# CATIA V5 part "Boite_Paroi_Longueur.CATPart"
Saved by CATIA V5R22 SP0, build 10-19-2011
Part number: Boite_Paroi_Longueur
Bounding box of the stored display mesh (mm): x -88 to 88, y 0 to 5, z -17.5 to 17.5
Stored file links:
  U:\S9A\PER\CAO\Assemblage\Reservoir_Boite\Boite\Boite_Paroi_Longueur.CATPart
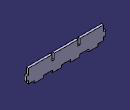
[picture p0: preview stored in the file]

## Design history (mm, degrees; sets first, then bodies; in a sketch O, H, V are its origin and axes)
Body1 (main body)
  Sketch1 on zx-plane, origin (0, 0, 0), H (-1, 0, 0), V (0, 0, 1)
    line L1 (-88, 17.5) -> (88, 17.5)
    line L2 (88, 17.5) -> (88, -17.5)
    line L3 (88, -17.5) -> (-88, -17.5)
    line L4 (-88, -17.5) -> (-88, 17.5)
    length L1 = 176
    length L4 = 35
    horizontal: L1 H, L3 H
    vertical: L2 V, L4 V
    symmetry: L4 L2 V, L3 L1 H
  Pad1: profile Sketch1, direction (0, 1, 0), length 5
  Sketch2 on end face of Pad1, origin (0, 5, 0), H (-1, 0, 0), V (0, 0, 1)
    point P1 (-88, -17.5)
    line L1 (-88, -17.5) -> (-70, -17.5)
    line L2 (-70, -17.5) -> (-70, -12.5)
    line L3 (-70, -12.5) -> (-88, -12.5)
    line L4 (-88, -12.5) -> (-88, -17.5)
    point P2 (-70, -17.5)
    point P3 (-70, -12.5)
    point P4 (-88, -12.5)
    reference projected point E1 (-88, -17.5) from vertex [face of Pad1 from Sketch1.L3 | end face of Pad1 | face of Pad1 from Sketch1.L4]
    point P5 (88, -17.5)
    point P6 (70, -17.5)
    point P7 (70, -12.5)
    point P8 (88, -12.5)
    line L5 (88, -17.5) -> (70, -17.5)
    line L6 (70, -17.5) -> (70, -12.5)
    line L7 (70, -12.5) -> (88, -12.5)
    line L8 (88, -12.5) -> (88, -17.5)
    length L4 = 5
    length L1 = 18
    horizontal: L1 H, L3 H
    vertical: L2 V, L4 V
    coincidence: P1 E1
    symmetry: P1 P5 V, P2 P6 V, P3 P7 V, P4 P8 V, L1 L5 V, L2 L6 V, L3 L7 V, L4 L8 V
  Pocket1: profile Sketch2, direction (0, -1, 0), through (limit type 6)
  Sketch3 on end face of Pad1, origin (0, 5, 0), H (-1, 0, 0), V (0, 0, 1)
    point P1 (-88, 17.5)
    line L1 (-88, 17.5) -> (-83, 17.5)
    line L2 (-83, 17.5) -> (-83, 4.5)
    line L3 (-83, 4.5) -> (-88, 4.5)
    line L4 (-88, 4.5) -> (-88, 17.5)
    point P2 (-83, 17.5)
    point P3 (-83, 4.5)
    point P4 (-88, 4.5)
    reference projected point E1 (-88, 17.5) from vertex [face of Pad1 from Sketch1.L1 | end face of Pad1 | face of Pad1 from Sketch1.L4]
    point P5 (-88, -5.5)
    line L5 (-88, -5.5) -> (-83, -5.5)
    line L6 (-83, -5.5) -> (-83, -12.5)
    line L7 (-83, -12.5) -> (-88, -12.5)
    line L8 (-88, -12.5) -> (-88, -5.5)
    point P6 (-83, -5.5)
    point P7 (-83, -12.5)
    point P8 (-88, -12.5)
    reference projected point E2 (-88, -12.5) from vertex [end face of Pad1 | face of Pad1 from Sketch1.L4 | face of Pocket1 from Sketch2.L3]
    point P9 (88, 17.5)
    point P10 (83, 17.5)
    point P11 (83, 4.5)
    point P12 (88, 4.5)
    point P13 (88, -5.5)
    point P14 (83, -5.5)
    point P15 (83, -12.5)
    point P16 (88, -12.5)
    line L9 (88, 17.5) -> (83, 17.5)
    line L10 (83, 17.5) -> (83, 4.5)
    line L11 (83, 4.5) -> (88, 4.5)
    line L12 (88, 4.5) -> (88, 17.5)
    line L13 (88, -5.5) -> (83, -5.5)
    line L14 (83, -5.5) -> (83, -12.5)
    line L15 (83, -12.5) -> (88, -12.5)
    line L16 (88, -12.5) -> (88, -5.5)
    length L4 = 13
    length L8 = 7
    length L1 = 5
    horizontal: L1 H, L3 H, L5 H, L7 H
    vertical: L2 V, L4 V, L6 V, L8 V
    coincidence: P1 E1, P8 E2, L6 L2
    symmetry: P1 P9 V, P2 P10 V, P3 P11 V, P4 P12 V, P5 P13 V, P6 P14 V, P7 P15 V, P8 P16 V, L1 L9 V, L2 L10 V, L3 L11 V, L4 L12 V, L5 L13 V, L6 L14 V, L7 L15 V, L8 L16 V
  Pocket2: profile Sketch3, direction (0, -1, 0), through (limit type 6)
  Sketch4 on end face of Pad1, origin (0, 5, 0), H (-1, 0, 0), V (0, 0, 1)
    line L1 (-50, -12.5) -> (-30, -12.5)
    line L2 (-30, -12.5) -> (-30, -17.5)
    line L3 (-30, -17.5) -> (-50, -17.5)
    line L4 (-50, -17.5) -> (-50, -12.5)
    reference projected line E1 (-88, -17.5) -> (88, -17.5) from edge [face of Pad1 from Sketch1.L3 | end face of Pad1]
    reference projected line E2 (-70, -17.5) -> (-70, -12.5) from edge [end face of Pad1 | face of Pocket1 from Sketch2.L2]
    reference projected line E3 (-70, -12.5) -> (-88, -12.5) from edge [end face of Pad1 | face of Pocket1 from Sketch2.L3]
    distance L4 E2 = 20
    length L3 = 20
    horizontal: L1 H, L3 H
    vertical: L2 V, L4 V
    coincidence: L3 E1, L1 E3
  Pocket3: profile Sketch4, direction (0, -1, 0), through (limit type 6)
  RectPattern1: of Pocket3, direction 1 instances 3, spacing 40, along edge [face of Pad1 from Sketch1.L3 | end face of Pad1]
  Sketch5 on end face of Pad1, origin (0, 5, 0), H (-1, 0, 0), V (0, 0, 1)
    point P1 (-31, 17.5)
    line L1 (-31, 17.5) -> (-26, 17.5)
    line L2 (-26, 17.5) -> (-26, 5.5)
    line L3 (-26, 5.5) -> (-31, 5.5)
    line L4 (-31, 5.5) -> (-31, 17.5)
    point P2 (-26, 17.5)
    point P3 (-26, 5.5)
    point P4 (-31, 5.5)
    reference projected line E1 (88, 17.5) -> (-88, 17.5) from edge [face of Pad1 from Sketch1.L1 | end face of Pad1]
    point P5 (31, 17.5)
    point P6 (26, 17.5)
    point P7 (26, 5.5)
    point P8 (31, 5.5)
    line L5 (31, 17.5) -> (26, 17.5)
    line L6 (26, 17.5) -> (26, 5.5)
    line L7 (26, 5.5) -> (31, 5.5)
    line L8 (31, 5.5) -> (31, 17.5)
    length L1 = 5
    length L4 = 12
    distance L2 V = 26
    horizontal: L1 H, L3 H
    vertical: L2 V, L4 V
    coincidence: L1 E1
    symmetry: P1 P5 V, P2 P6 V, P3 P7 V, P4 P8 V, L1 L5 V, L2 L6 V, L3 L7 V, L4 L8 V
  Pocket4: profile Sketch5, direction (0, -1, 0), through (limit type 6)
